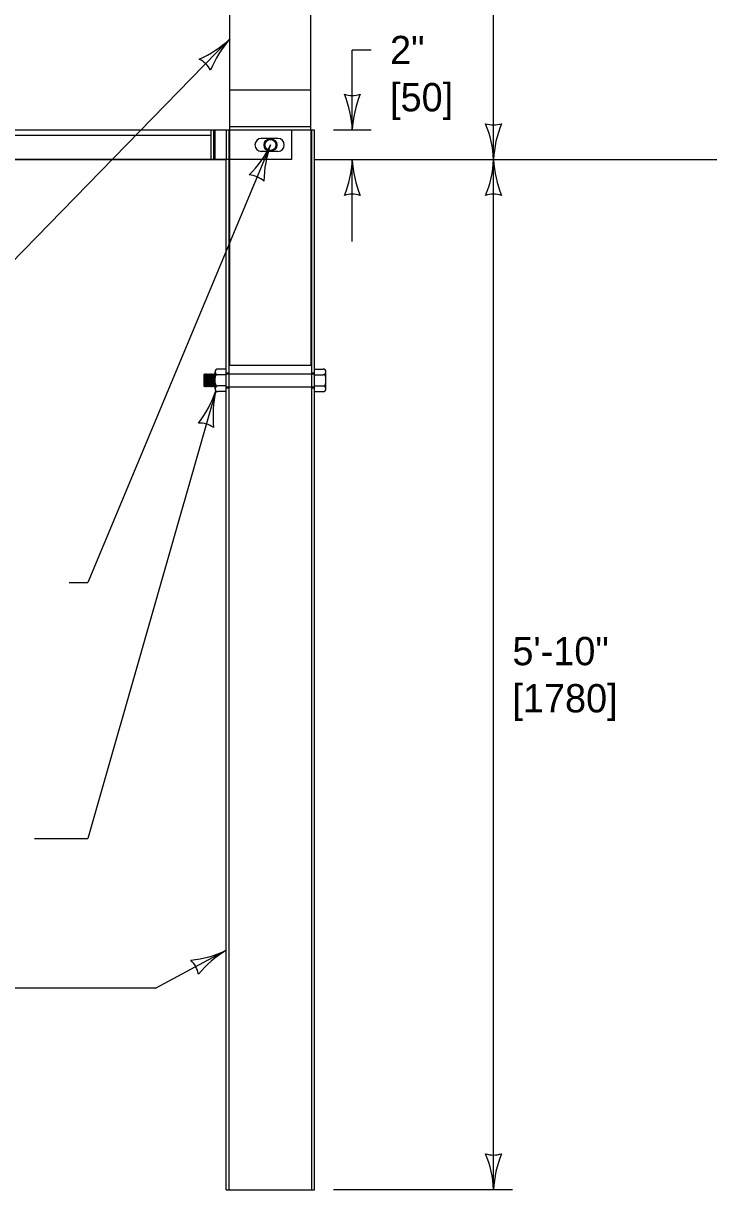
# Model space of a CAD drawing. Extents: x 49991.4 to 50021, y 49987.6 to 50011.4.
# Drawn here: x 50003.165 to 50004.618, y 49992.871 to 49995.344 of the extents above; entities that cross this region are included whole.
import ezdxf

# ---------------------------------------------------------------- set-up
doc = ezdxf.new("R2010")
doc.units = 0
for name, color, linetype in [('Level 1', 7, 'Continuous'), ('Level 2', 7, 'Continuous'), ('Level 3', 7, 'Continuous'), ('Level 4', 7, 'Continuous')]:
    doc.layers.add(name, color=color, linetype=linetype)

msp = doc.modelspace()

# ---------------------------------------------------------------- linework, layer by layer
at = {"layer": 'Level 1'}
for p, q in [((50003.6032, 49995.1175), (50003.6032, 49995.6473)), ((50003.7748, 49995.1175), (50003.7748, 49995.6473)), ((50003.7339, 49995.1175), (50001.3004, 49995.1175)), ((50003.5624, 49995.1175), (50003.5624, 49995.0551)), ((50003.5721, 49995.0551), (50003.5721, 49995.1175)), ((50003.7826, 49995.1175), (50003.5954, 49995.1175)), ((50003.7339, 49995.1175), (50003.7339, 49995.0551)), ((50003.7826, 49992.8711), (50003.7826, 49995.1175)), ((50003.7047, 49995.1), (50003.6696, 49995.1)), ((50003.6696, 49995.0727), (50003.7047, 49995.0727)), ((50003.7339, 49995.0551), (50001.3004, 49995.0551)), ((50001.4391, 49995.0551), (50003.5952, 49995.0551)), ((50003.5954, 49992.8711), (50003.5954, 49995.0551)), ((50003.7828, 49995.0551), (50004.767, 49995.0551)), ((50003.5485, 49994.5991), (50003.5498, 49994.6008)), ((50003.5485, 49994.5991), (50003.5498, 49994.5735)), ((50003.5485, 49994.5752), (50003.5485, 49994.5991)), ((50003.5498, 49994.6008), (50003.5512, 49994.5752)), ((50003.5512, 49994.5991), (50003.5498, 49994.6008)), ((50003.5512, 49994.5991), (50003.5525, 49994.6008)), ((50003.5512, 49994.5991), (50003.5525, 49994.5735)), ((50003.5539, 49994.5991), (50003.5525, 49994.6008)), ((50003.5525, 49994.6008), (50003.5539, 49994.5752)), ((50003.5539, 49994.5991), (50003.5552, 49994.6008)), ((50003.5539, 49994.5991), (50003.5552, 49994.5735)), ((50003.5565, 49994.5991), (50003.5552, 49994.6008)), ((50003.5552, 49994.6008), (50003.5565, 49994.5752)), ((50003.5565, 49994.5991), (50003.5578, 49994.6008)), ((50003.5565, 49994.5991), (50003.5578, 49994.5735)), ((50003.5592, 49994.5991), (50003.5578, 49994.6008)), ((50003.5578, 49994.6008), (50003.5592, 49994.5752)), ((50003.5592, 49994.5991), (50003.5605, 49994.6008)), ((50003.5592, 49994.5991), (50003.5605, 49994.5735)), ((50003.5619, 49994.5991), (50003.5605, 49994.6008)), ((50003.5605, 49994.6008), (50003.5619, 49994.5752)), ((50003.5619, 49994.5991), (50003.5632, 49994.6008)), ((50003.5619, 49994.5991), (50003.5632, 49994.5735)), ((50003.5646, 49994.5991), (50003.5632, 49994.6008)), ((50003.5632, 49994.6008), (50003.5646, 49994.5752)), ((50003.5646, 49994.5991), (50003.5659, 49994.6008)), ((50003.5646, 49994.5991), (50003.5659, 49994.5735)), ((50003.5672, 49994.5991), (50003.5659, 49994.6008)), ((50003.5659, 49994.6008), (50003.5672, 49994.5752)), ((50003.5672, 49994.5991), (50003.5685, 49994.6008)), ((50003.5672, 49994.5991), (50003.5685, 49994.5735)), ((50003.5699, 49994.5991), (50003.5685, 49994.6008)), ((50003.5685, 49994.6008), (50003.5699, 49994.5752)), ((50003.5699, 49994.5991), (50003.5712, 49994.6008)), ((50003.5699, 49994.5991), (50003.5712, 49994.5735)), ((50003.5712, 49994.6008), (50003.5716, 49994.5964)), ((50003.5716, 49994.6004), (50003.5712, 49994.6008)), ((50003.5716, 49994.5692), (50003.5716, 49994.6051)), ((50003.5955, 49994.611), (50003.5774, 49994.611)), ((50003.5955, 49994.599), (50003.5774, 49994.599)), ((50003.7827, 49994.611), (50003.8008, 49994.611)), ((50003.7827, 49994.599), (50003.8008, 49994.599)), ((50003.8066, 49994.5692), (50003.8066, 49994.6051)), ((50003.5498, 49994.5735), (50003.5485, 49994.5752)), ((50003.5498, 49994.5735), (50003.5512, 49994.5752)), ((50003.5525, 49994.5735), (50003.5512, 49994.5752)), ((50003.5525, 49994.5735), (50003.5539, 49994.5752)), ((50003.5552, 49994.5735), (50003.5539, 49994.5752)), ((50003.5552, 49994.5735), (50003.5565, 49994.5752)), ((50003.5578, 49994.5735), (50003.5565, 49994.5752)), ((50003.5578, 49994.5735), (50003.5592, 49994.5752)), ((50003.5605, 49994.5735), (50003.5592, 49994.5752)), ((50003.5605, 49994.5735), (50003.5619, 49994.5752)), ((50003.5632, 49994.5735), (50003.5619, 49994.5752)), ((50003.5632, 49994.5735), (50003.5646, 49994.5752)), ((50003.5659, 49994.5735), (50003.5646, 49994.5752)), ((50003.5659, 49994.5735), (50003.5672, 49994.5752)), ((50003.5685, 49994.5735), (50003.5672, 49994.5752)), ((50003.5685, 49994.5735), (50003.5699, 49994.5752)), ((50003.5712, 49994.5735), (50003.5699, 49994.5752)), ((50003.5712, 49994.5735), (50003.5716, 49994.5739)), ((50003.5955, 49994.5752), (50003.5774, 49994.5752)), ((50003.5955, 49994.5633), (50003.5774, 49994.5633)), ((50003.7827, 49994.5752), (50003.8008, 49994.5752)), ((50003.7827, 49994.5633), (50003.8008, 49994.5633)), ((50003.5954, 49992.8711), (50003.7826, 49992.8711))]:
    msp.add_line(p, q, dxfattribs=at)
for radius in [0.0136, 0.0117]:
    msp.add_circle((50003.689, 49995.0863), radius, dxfattribs=at)
for centre, radius, start, end in [((50003.6696, 49995.0863), 0.0137, 90, 270), ((50003.7047, 49995.0863), 0.0137, 270, 90), ((50003.5775, 49994.6051), 0.00585, 90.1602, 180.1602), ((50003.5776, 49994.605), 0.00596, 178.7945, 268.7945), ((50003.5774, 49994.5932), 0.00585, 90.0618, 177.1409), ((50003.8007, 49994.6051), 0.00585, 359.8398, 89.8398), ((50003.8006, 49994.605), 0.00596, 271.2055, 1.2055), ((50003.8007, 49994.5932), 0.00585, 2.8591, 89.9382), ((50003.5775, 49994.5811), 0.00588, 182.0518, 269.5951), ((50003.5775, 49994.5693), 0.00593, 90.896, 180.896), ((50003.5775, 49994.5692), 0.00588, 179.5221, 269.5221), ((50003.8007, 49994.5811), 0.00588, 270.4049, 357.9482), ((50003.8007, 49994.5693), 0.00593, 359.104, 89.104), ((50003.8007, 49994.5692), 0.00588, 270.4779, 0.4779)]:
    msp.add_arc(centre, radius, start, end, dxfattribs=at)
at = {"layer": 'Level 3'}
for p, q in [((50004.1621, 49995.0551), (50004.1621, 49995.8348)), ((50003.0572, 49994.752), (50003.6032, 49995.311)), ((50003.9026, 49995.2875), (50003.8626, 49995.2875)), ((50003.8626, 49995.1175), (50003.8626, 49995.2875)), ((50003.9026, 49995.1175), (50003.8226, 49995.1175)), ((50003.689, 49995.0863), (50003.302, 49994.1584)), ((50003.8626, 49994.8817), (50003.8626, 49995.0551)), ((50004.1621, 49992.8711), (50004.1621, 49995.0551)), ((50003.5733, 49994.565), (50003.302, 49993.616)), ((50003.262, 49994.1584), (50003.302, 49994.1584)), ((50003.1885, 49993.616), (50003.302, 49993.616)), ((50003.4449, 49993.2982), (50003.5954, 49993.3787)), ((50003.4449, 49993.2982), (50002.8169, 49993.2982)), ((50004.2021, 49992.8711), (50003.8226, 49992.8711))]:
    msp.add_line(p, q, dxfattribs=at)
for centre, radius, start, end in [((50003.4507, 49995.4728), 0.2223, 293.1328, 313.3163), ((50003.7777, 49995.1566), 0.233, 138.5041, 157.7539), ((50003.5136, 49995.2193), 0.0548, 27.8156, 63.5379), ((50003.8626, 49995.2458), 0.0548, 252.1388, 287.8612), ((50003.6299, 49995.106), 0.233, 2.8273, 22.0772), ((50004.0847, 49995.1084), 0.2223, 157.456, 177.6395), ((50004.1621, 49995.1834), 0.0548, 252.1388, 287.8612), ((50003.9294, 49995.0436), 0.233, 2.8273, 22.0772), ((50004.3843, 49995.046), 0.2223, 157.456, 177.6395), ((50003.4875, 49995.1803), 0.2223, 314.8181, 335.0016), ((50003.9082, 49995.0074), 0.233, 160.1894, 179.4393), ((50003.6405, 49995.0643), 0.2223, 337.456, 357.6395), ((50004.0953, 49995.0666), 0.233, 182.8273, 202.0772), ((50003.94, 49995.0643), 0.2223, 337.456, 357.6395), ((50004.3948, 49995.0666), 0.233, 182.8273, 202.0772), ((50003.6396, 49994.968), 0.0548, 49.5009, 85.2233), ((50003.8626, 49994.9269), 0.0548, 72.1388, 107.8612), ((50004.1621, 49994.9269), 0.0548, 72.1388, 107.8612), ((50003.3622, 49994.6349), 0.2223, 321.5038, 341.6873), ((50003.8002, 49994.5121), 0.233, 166.8751, 186.1249), ((50003.5381, 49994.4418), 0.0548, 56.1866, 91.909), ((50003.4987, 49993.5789), 0.2223, 275.5851, 295.7686), ((50003.7152, 49993.1789), 0.233, 120.9564, 140.2062), ((50003.4823, 49993.3182), 0.0548, 10.2679, 45.9903), ((50004.1621, 49992.9994), 0.0548, 252.1388, 287.8612), ((50003.9294, 49992.8596), 0.233, 2.8273, 22.0772), ((50004.3843, 49992.862), 0.2223, 157.456, 177.6395)]:
    msp.add_arc(centre, radius, start, end, dxfattribs=at)
at = {"layer": 'Level 4'}
for p, q in [((50003.6032, 49995.2033), (50003.7748, 49995.2033)), ((50001.4719, 49995.1068), (50003.5624, 49995.1068)), ((50003.5682, 49995.1175), (50003.5682, 49995.0551)), ((50003.5954, 49995.1175), (50003.5952, 49995.0551)), ((50003.6013, 49992.8711), (50003.6013, 49995.1175)), ((50003.6032, 49995.1253), (50003.7748, 49995.1253)), ((50003.6032, 49994.6183), (50003.6032, 49995.1175)), ((50003.7748, 49995.1175), (50003.7748, 49994.6183)), ((50003.7767, 49992.8711), (50003.7767, 49995.1175)), ((50003.7748, 49994.6183), (50003.6032, 49994.6183)), ((50003.5954, 49994.6027), (50003.6013, 49994.6027)), ((50003.5955, 49994.6008), (50003.7827, 49994.6008)), ((50003.7767, 49994.6027), (50003.7826, 49994.6027)), ((50003.5954, 49994.5715), (50003.6013, 49994.5715)), ((50003.5955, 49994.5735), (50003.7827, 49994.5735)), ((50003.7767, 49994.5715), (50003.7826, 49994.5715))]:
    msp.add_line(p, q, dxfattribs=at)

# ---------------------------------------------------------------- texts
at = {"layer": 'Level 2'}
for s, p in [('2"', (50003.9426, 49995.2575)), ('[50]', (50003.9426, 49995.1575)), ('5\'-10"', (50004.2021, 49993.9831)), ('[1780]', (50004.2021, 49993.8831))]:
    msp.add_text(s, height=0.06, dxfattribs=at).set_placement(p)

doc.saveas('drawing.dxf')
